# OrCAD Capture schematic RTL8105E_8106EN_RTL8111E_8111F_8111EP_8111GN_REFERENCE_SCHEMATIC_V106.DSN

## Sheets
1 P07. Change Note: title: RTL8105E/8111E/8111F/8111EP/8111GN/8106EN Reference Schematic: Change Notes; rev: A1; company: Realtek Semiconductor Corp.; note: RTL8105E/8111E/8111F/8111EP/8111GN/8106EN Reference Schematic; note: No.2, Innovation Road II, Hsinchu Science Park, Hsinchu 300, Taiwan
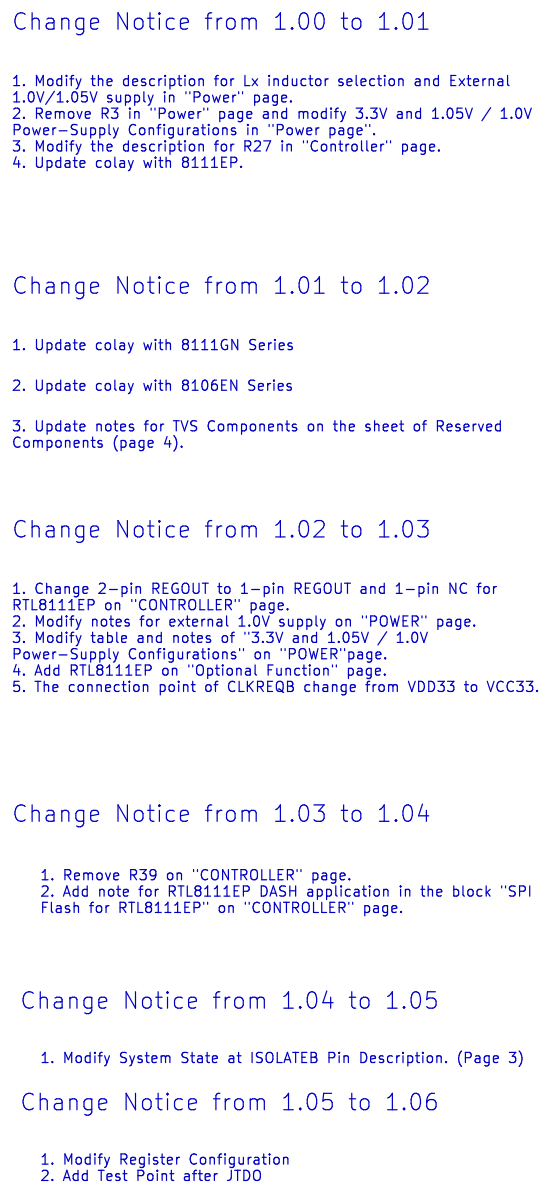
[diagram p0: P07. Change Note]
2 P06. R-BOM: title: RTL8105E/8111E/8111F/8111EP/8111GN/8106EN Reference Schematic: R-BOM
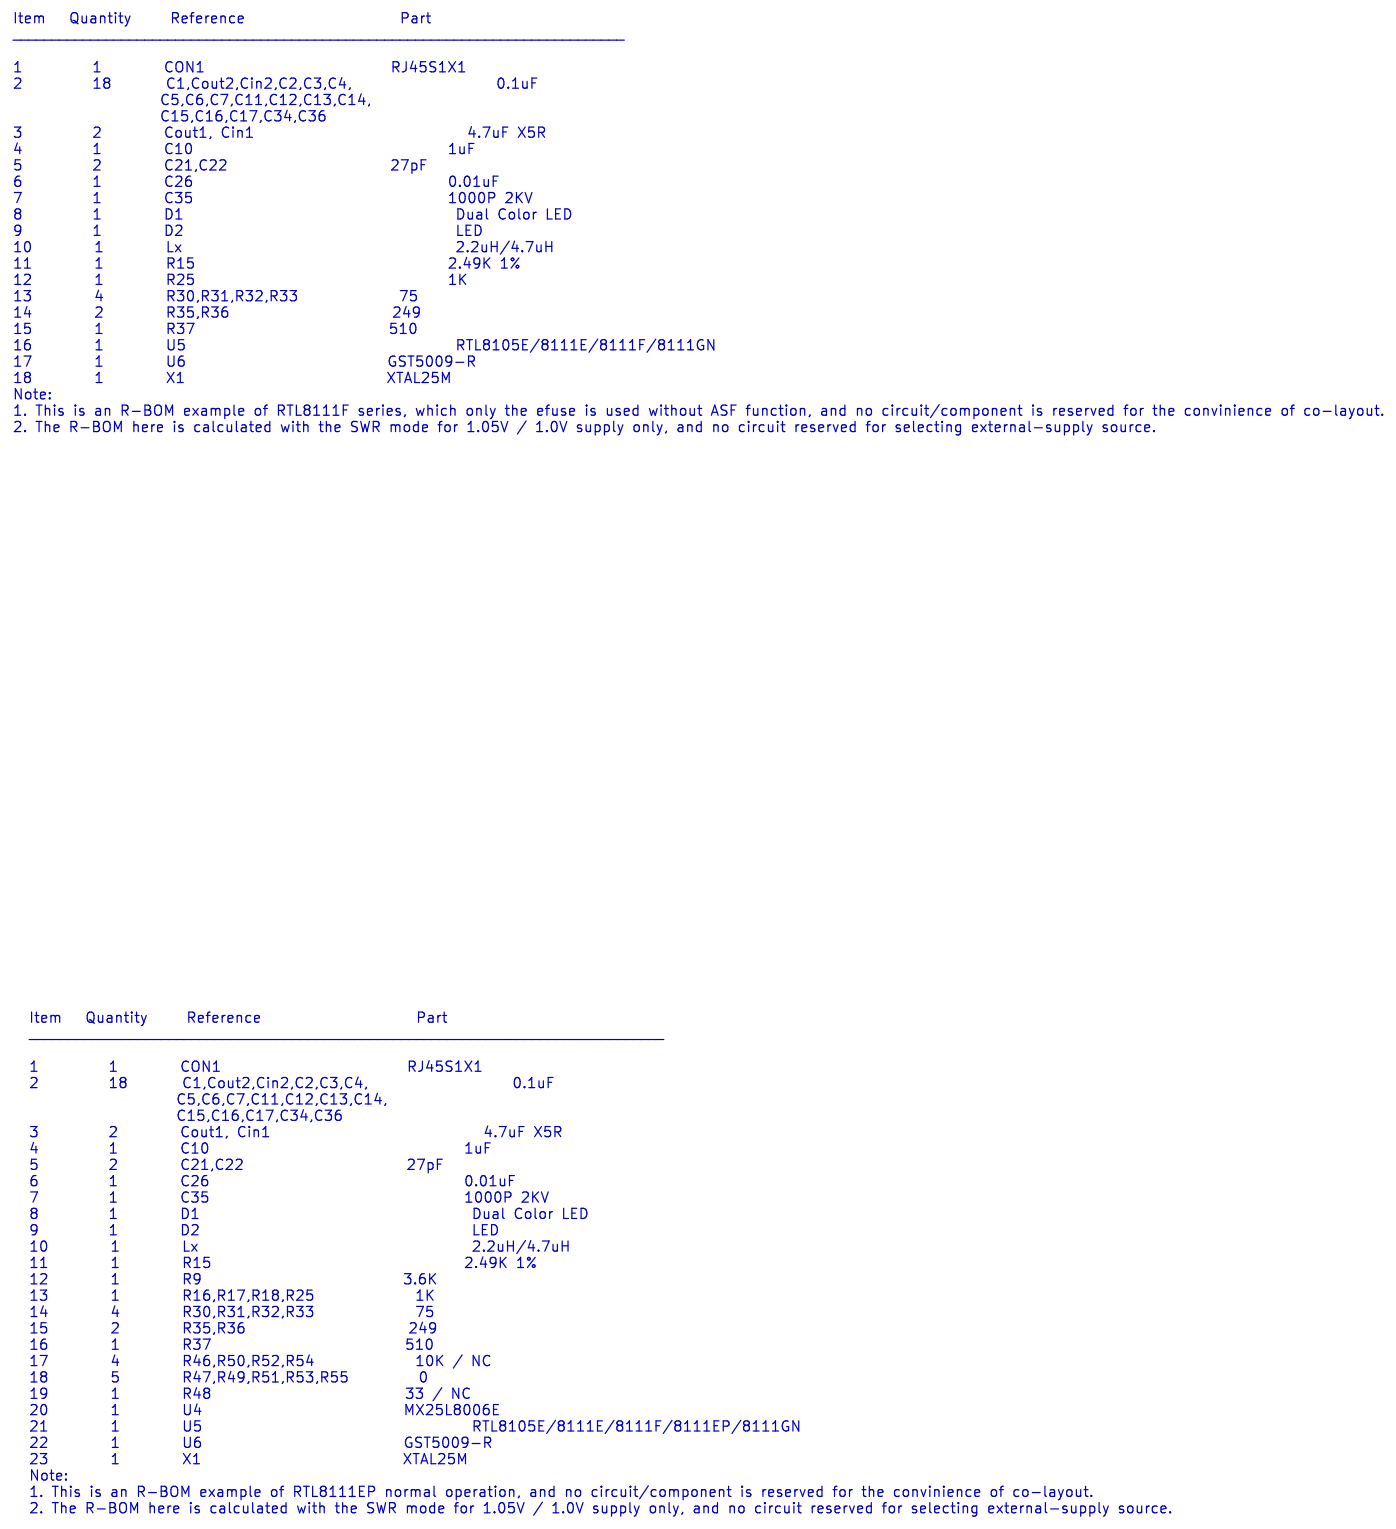
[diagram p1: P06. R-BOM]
3 P04. Reserved Components: size A3; title: RTL8105E/8111E/8111F/8111EP/8111GN/8106EN: Reserved Components
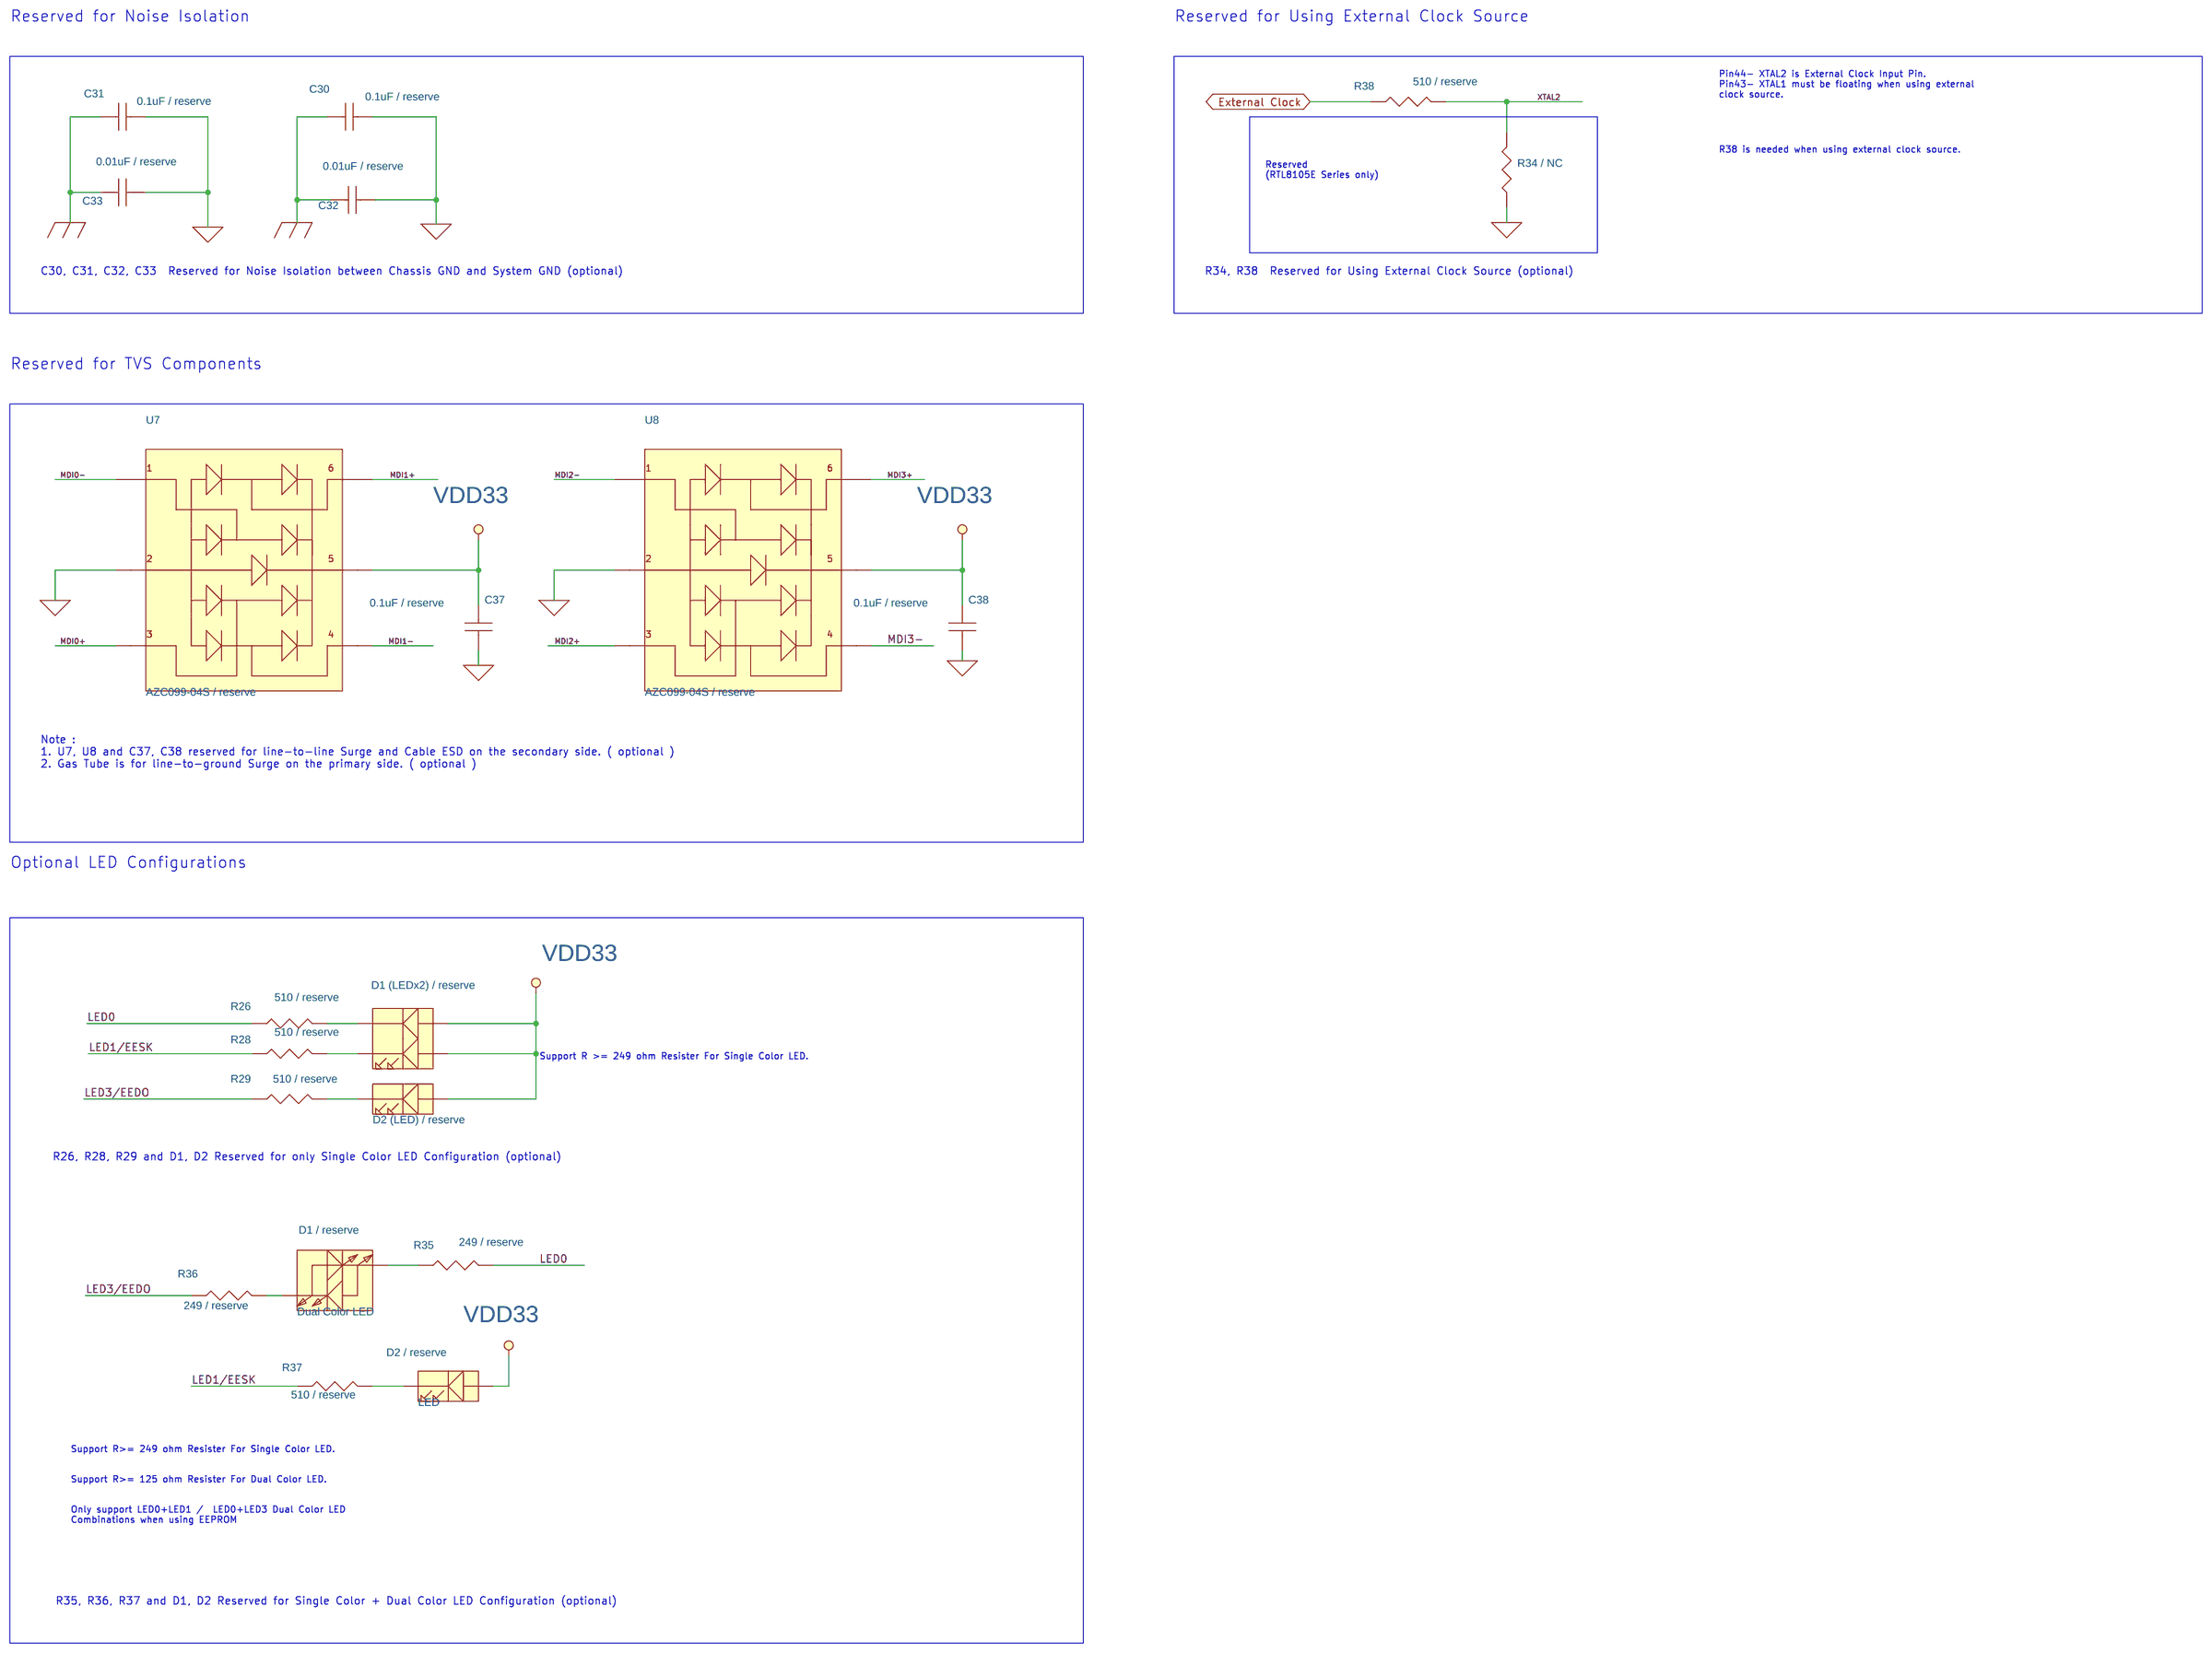
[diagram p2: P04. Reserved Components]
4 P05. Optional Function: size A4; title: RTL8105E/8111E/8111F/8111EP/8111GN/8106EN Reference Schematic: Optional Function
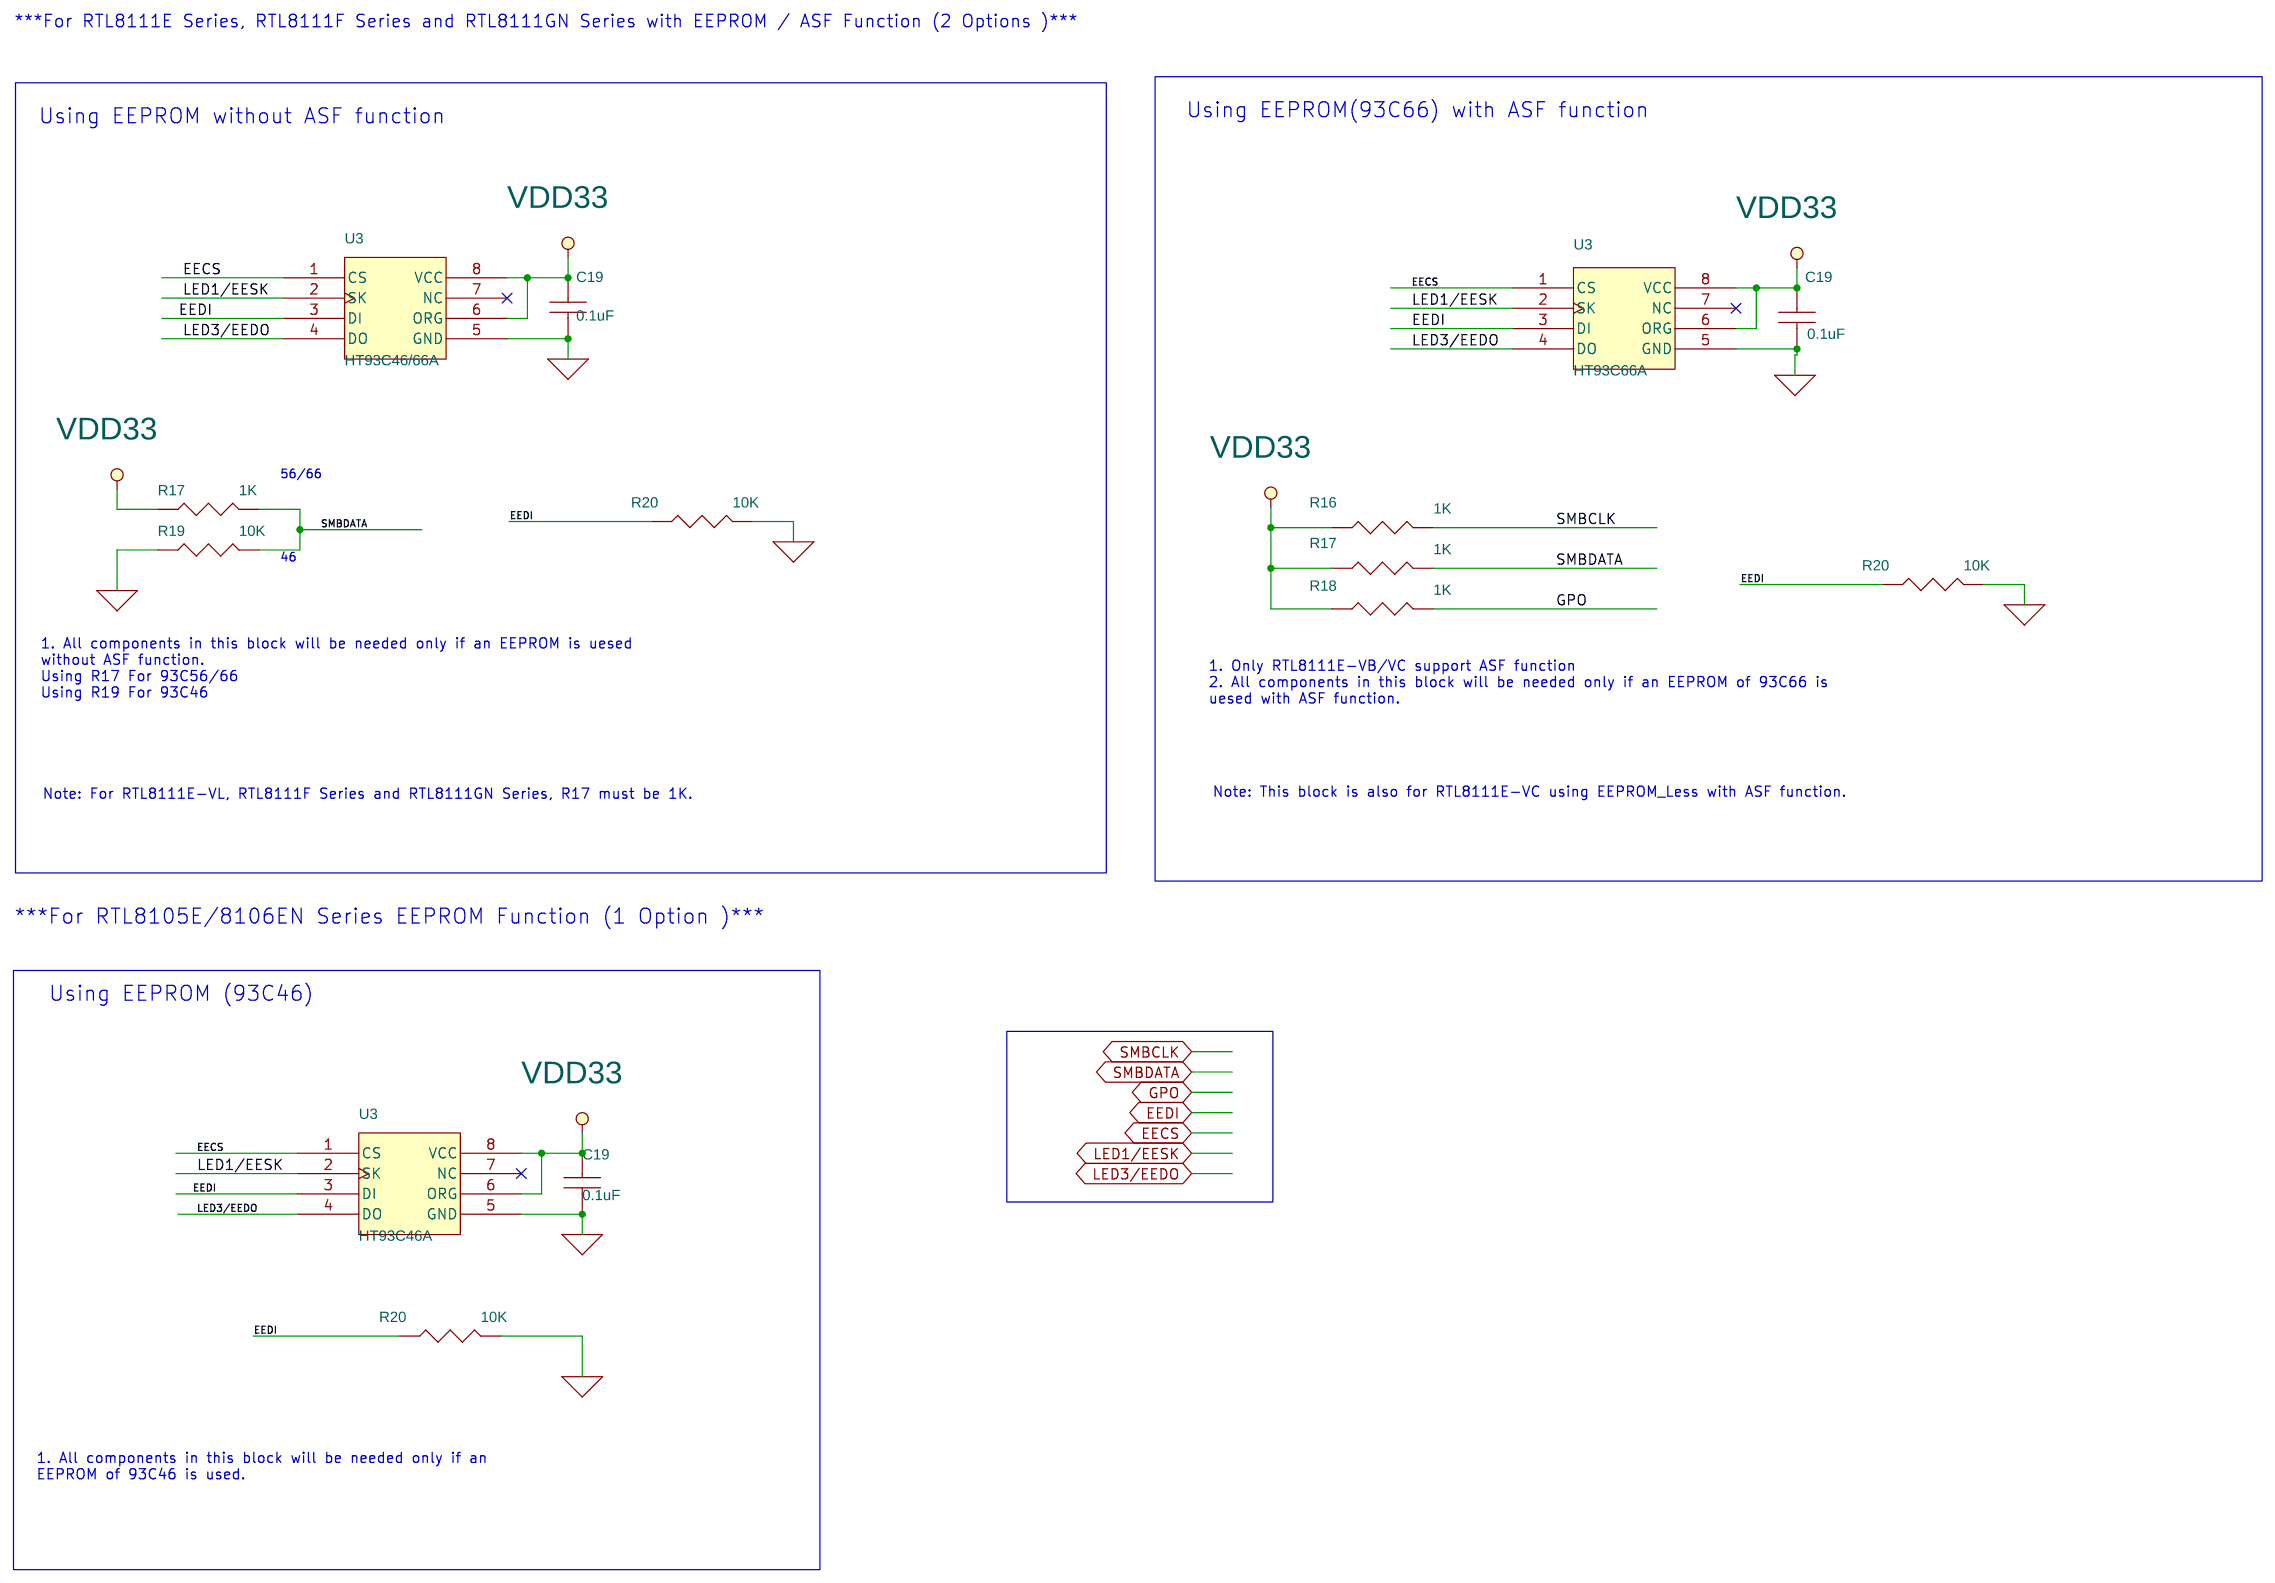
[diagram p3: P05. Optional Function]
5 P01. Index: title: RTL8105E/8111E/8111F/8111EP/8111GN/8106EN Reference Schematic: Index
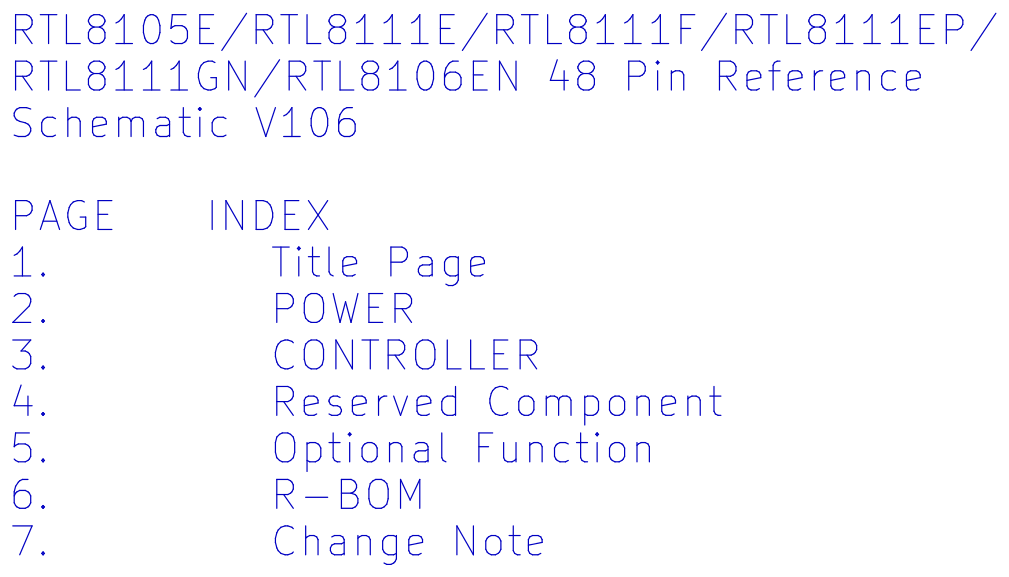
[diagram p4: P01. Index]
6 P02. POWER: size A3; title: RTL8105E/8111E/8111F/8111EP/8111GN/8106EN Reference Schematic: Power
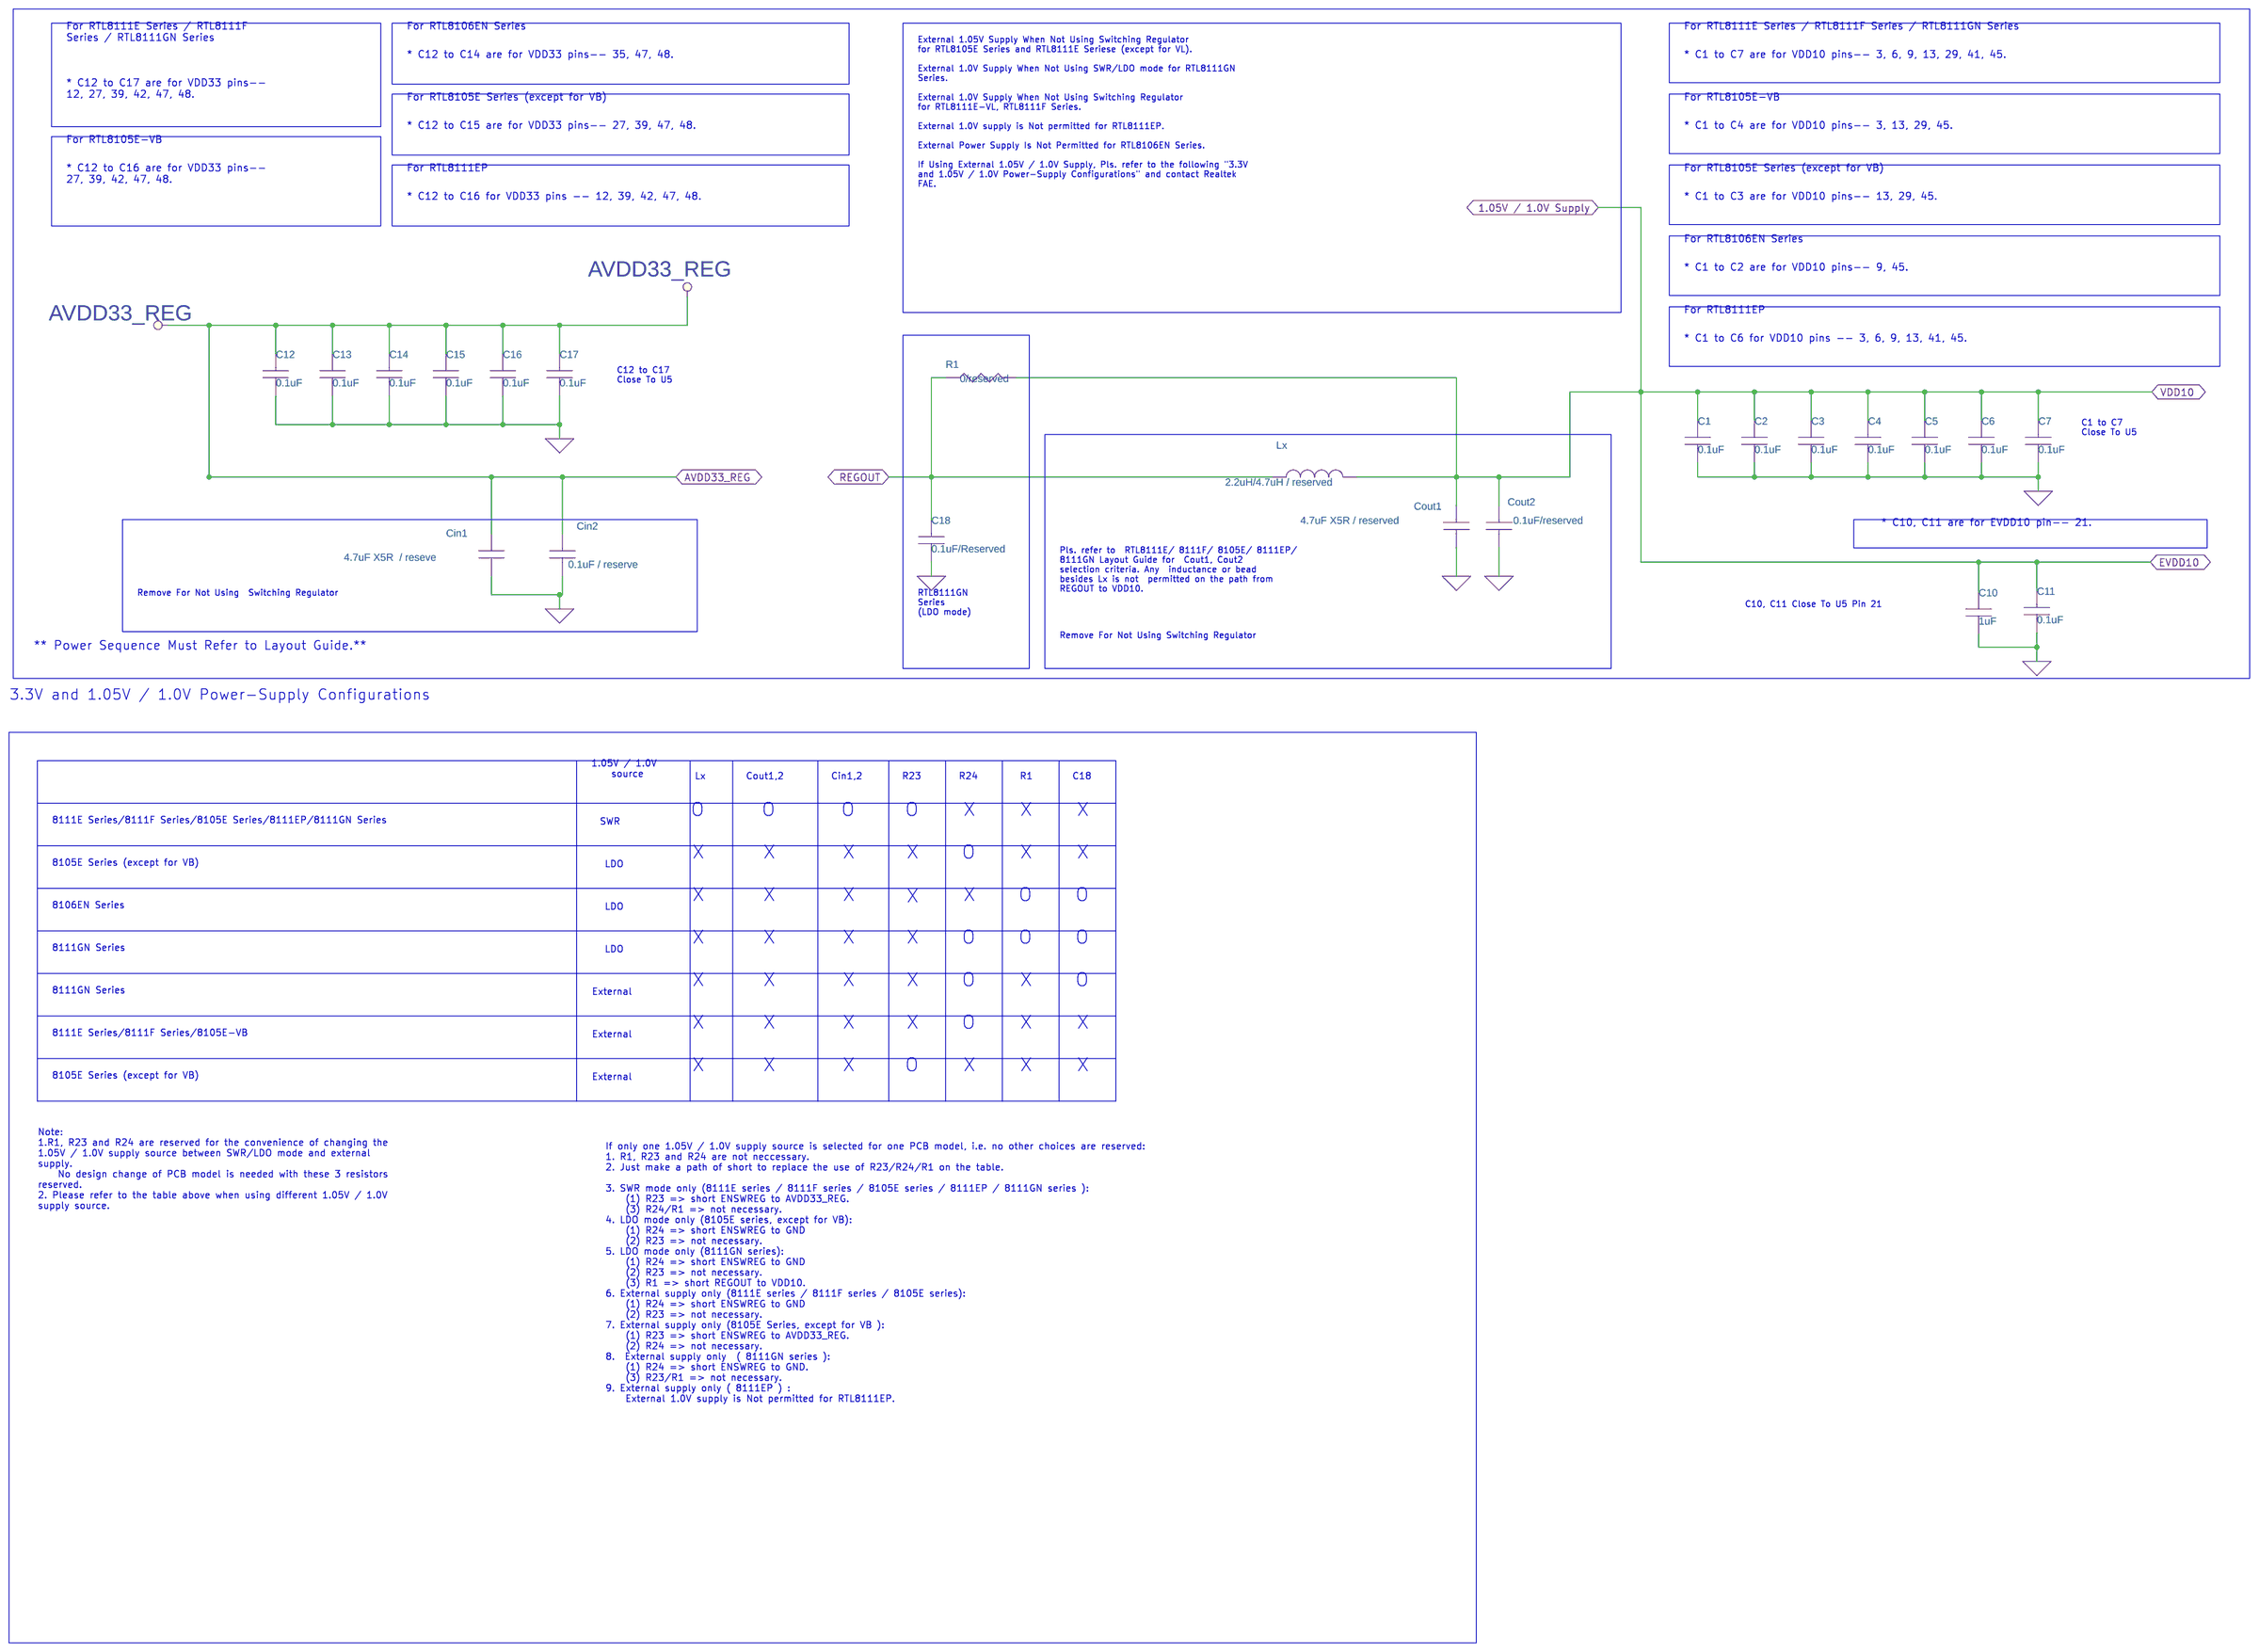
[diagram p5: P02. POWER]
7 P03. CONTROLLER: size A2; title: RTL8105E/8111E/8111F/8111EP/8111GN/8106EN Reference Schematic: Controller
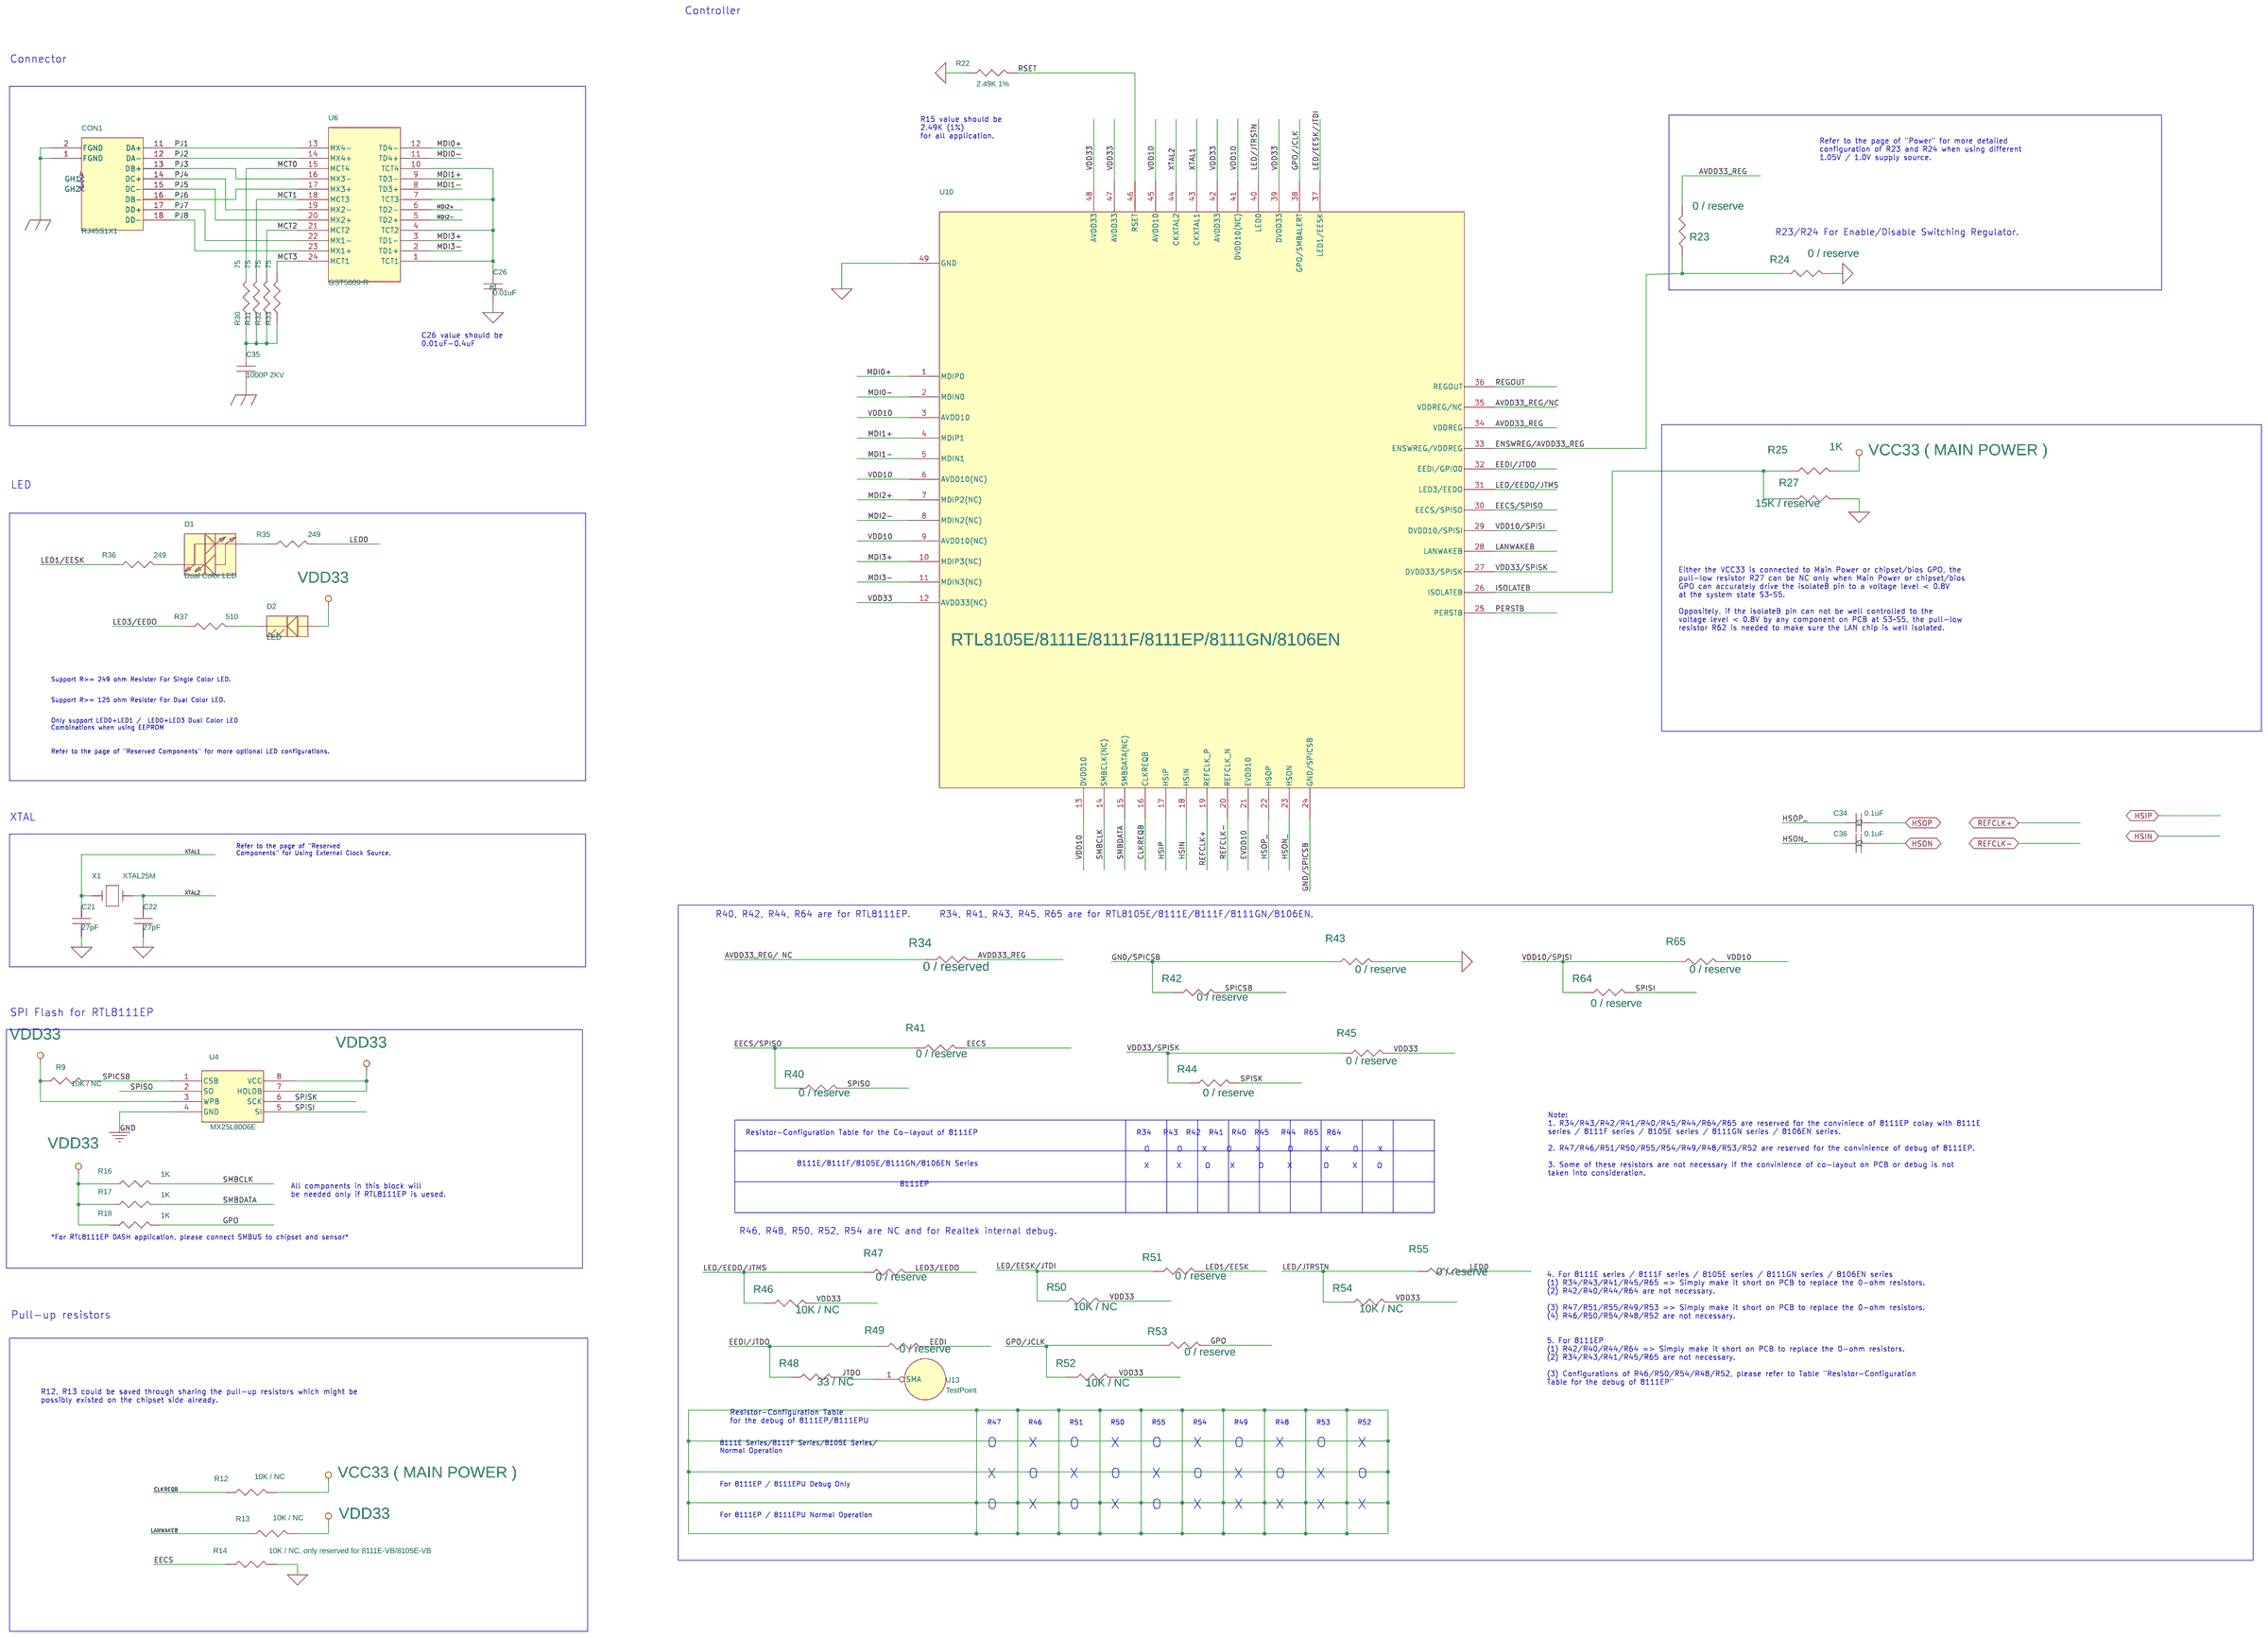
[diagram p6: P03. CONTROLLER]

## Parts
sheet P02. POWER
C1  0.1uF  [C0402C]
C2  0.1uF  [C0402C]
C3  0.1uF  [C0402C]
C4  0.1uF  [C0402C]
C5  0.1uF  [C0402C]
C6  0.1uF  [C0402C]
C7  0.1uF  [C0402C]
C10  1uF  [C0402C]
C11  0.1uF  [C0402C]
C12  0.1uF  [C0402C]
C13  0.1uF  [C0402C]
C14  0.1uF  [C0402C]
C15  0.1uF  [C0402C]
C16  0.1uF  [C0402C]
C17  0.1uF  [C0402C]
C18  0.1uF/Reserved  [C0402C]
Cin1  4.7uF X5R  / reseve  [C1206C]
Cin2  0.1uF / reserve  [C0402C]
Cout1  4.7uF X5R / reserved  [C0805C]
Cout2  0.1uF/reserved  [C0402C]
Lx  2.2uH/4.7uH / reserved  [L\5X5\3.15]
R1  0/reserved  [R0402R]
sheet P03. CONTROLLER
C21  27pF  [C0402C]
C22  27pF  [C0402C]
C26  0.01uF  [C0402C]
C34  0.1uF
C35  1000P 2KV  [C1206C]
C36  0.1uF
CON1  RJ45S1X1  [RJ45S1X1]
D1  Dual Color LED  [LED2X2]
D2  LED  [LED]
R9  10K / NC  [R0402R]
R12  10K / NC  [R0402R]
R13  10K / NC  [R0402R]
R14  10K / NC, only reserved for 8111E-VB/8105E-VB  [R0402R]
R22  2.49K 1%  [R0402R]
R23  0 / reserve  [R0402R]
R24  0 / reserve  [R0402R]
R25  1K  [R0402R]
R27  15K / reserve  [R0402R]
R30  75  [R0402R]
R31  75  [R0402R]
R32  75  [R0402R]
R33  75  [R0402R]
R34  0 / reserved  [R0402R]
R40  0 / reserve  [R0402R]
R41  0 / reserve  [R0402R]
R42  0 / reserve  [R0402R]
R43  0 / reserve  [R0402R]
R44  0 / reserve  [R0402R]
R45  0 / reserve  [R0402R]
R46  10K / NC  [R0402R]
R47  0 / reserve  [R0402R]
R48  33 / NC  [R0402R]
R49  0 / reserve  [R0402R]
R50  10K / NC  [R0402R]
R51  0 / reserve  [R0402R]
R52  10K / NC  [R0402R]
R53  0 / reserve  [R0402R]
R54  10K / NC  [R0402R]
R55  0 / reserve  [R0402R]
R64  0 / reserve  [R0402R]
R65  0 / reserve  [R0402R]
U4  MX25L8006E  [SOIC8]
U6  GST5009-R  [GST5009-LFE9249-R]
U10  RTL8105E/8111E/8111F/8111EP/8111GN/8106EN  [QFN6x6-48]
U13  TestPoint  [SMA]
X1  XTAL25M  [XTAL]
sheet P04. Reserved Components
C30  0.1uF / reserve  [C0402C]
C31  0.1uF / reserve  [C0402C]
C32  0.01uF / reserve  [C0402C]
C33  0.01uF / reserve  [C0402C]
C37  0.1uF / reserve  [C0402C]
C38  0.1uF / reserve  [C0402C]
D1 (LEDx2) / reserve  LEDx2  [LED2X2]
D1 / reserve  Dual Color LED  [LED2X2]
D2 (LED) / reserve  LED  [LED]
D2 / reserve  LED  [LED]
R26  510 / reserve  [R0402R]
R28  510 / reserve  [R0402R]
R29  510 / reserve  [R0402R]
R34 / NC  NC  [R0402R]
R35  249 / reserve  [R0402R]
R35#2  249 / reserve  [R0402R]
R36  249 / reserve  [R0402R]
R36#2  249 / reserve  [R0402R]
R37  510 / reserve  [R0402R]
R37#2  510 / reserve  [R0402R]
R38  510 / reserve  [R0402R]
U7  AZC099-04S / reserve  [SOT23-6L]
U8  AZC099-04S / reserve  [SOT23-6L]
sheet P05. Optional Function
C19  0.1uF  [C0402C]
C19#2  0.1uF  [C0402C]
C19#3  0.1uF  [C0402C]
R16  1K  [R0402R]
R16#2  1K  [R0402R]
R17  1K  [R0402R]
R17#2  1K  [R0402R]
R17#3  1K  [R0402R]
R18  1K  [R0402R]
R18#2  1K  [R0402R]
R19  10K  [R0402R]
R20  10K  [R0402R]
R20#2  10K  [R0402R]
R20#3  10K  [R0402R]
U3  HT93C66A  [SO8-6-1.27]
U3#2  HT93C66A  [SO8-6-1.27]
U3#3  HT93C46A  [SO8-6-1.27]

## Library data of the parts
C1-C3 = CAPACITOR_NON-POL_0: ROOM: c_15
C4-C7 Cout1 Cout2 = CAPACITOR_NON-POL_0: ROOM: vdd18
C10 C11 = CAPACITOR_NON-POL_0: ROOM: vdd15
C12 C15 C16 = CAPACITOR_NON-POL_0: ROOM: 33vaux
C13 C14 C17-C19 C19#2 C19#3 C21 C22 C30-C33 C35 Cin1 Cin2 = CAPACITOR_NON-POL_0
Lx = INDUCTOR_0: ROOM: vdd18
R1 R9 R12-R14 R16 R16#2 R17 R17#2 R17#3 R18 R18#2 R19 R20 R20#2 R20#3 R22-R34 R34 / NC R35 R35#2 R36 R36#2 R37 R37#2 R38 R40-R55 R64 R65 = R
C26 = CAP_NP
C34 = CAP_NP_2
C36-C38 = CAP_NP_1
CON1 = RJ45_2
D1 D1 / reserve = LED_2
D2 D2 (LED) / reserve D2 / reserve = LED_3
U4 = 8-LEAD_SOIC_0
U6 = H5007
U10 = RL5877_84
U13 = SMA
X1 = CRYSTAL_0
D1 (LEDx2) / reserve = LED_1
U7 U8 = 9346_5
U3 U3#2 U3#3 = 9346_4

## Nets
AVDD33_REG: R23.2 R34.2 U10.34(VDDREG)
DGND: C1.2 C2.2 C3.2 C4.2 C5.2 C6.2 C7.2 C10.2 C11.2 C12.2 C13.2 C14.2 C15.2 C16.2 C17.2 C18.2 C19.2 C19#2.2 C19#3.2 C21.2 C22.2 C26.2 C30.2 C31.2 C32.2 C33.2 C37.2 C38.2 Cin1.2 Cin2.2 Cout1.2 Cout2.2 R14.2 R19.1 R20.2 R20#2.2 R20#3.2 R22.1 R24.2 R27.2 R34 / NC.1 R43.2 U3.5(GND) U3#2.5(GND) U3#3.5(GND) U7.2 U8.2 U10.49(GND)
ENSWREG/AVDD33_REG: R23.1 R24.1 U10.33(ENSWREG/VDDREG)
GND POWER: U4.4(GND)
VCC33 ( Main Power ): R12.2 R25.2
VDD10: R65.2 U10.3(AVDD10) U10.6(AVDD10(NC)) U10.9(AVDD10(NC)) U10.13(DVDD10) U10.41(DVDD10(NC)) U10.45(AVDD10)
VDD33: C12.1 C13.1 C14.1 C15.1 C16.1 C17.1 C19.1 C19#2.1 C19#3.1 C37.1 C38.1 Cin1.1 Cin2.1 D1 (LEDx2) / reserve.1 D1 (LEDx2) / reserve.2 D2.1 D2 (LED) / reserve.1 D2 / reserve.1 R9.1 R13.2 R16.1 R16#2.1 R17.1 R17#2.1 R17#3.1 R18.1 R18#2.1 R45.2 R46.2 R50.2 R52.2 R54.2 U3.6(ORG) U3.8(VCC) U3#2.6(ORG) U3#2.8(VCC) U3#3.6(ORG) U3#3.8(VCC) U4.3(WPB) U4.7(HOLDB) U4.8(VCC) U7.5 U8.5 U10.12(AVDD33(NC)) U10.39(DVDD33) U10.42(AVDD33) U10.47(AVDD33) U10.48(AVDD33)
1.05V / 1.0V Supply: C1.1 C2.1 C3.1 C4.1 C5.1 C6.1 C7.1 C10.1 C11.1 Cout1.1 Cout2.1 Lx.2 R1.2
  REFCLK+: U10.19(REFCLK_P)
 EEDI: U3.3(DI) U3#3.3(DI)
AVDD33_REG/ NC: R34.1
AVDD33_REG/NC: U10.35(VDDREG/NC)
CLKREQB: R12.1 U10.16(CLKREQB)
EECS: R14.1 R41.2
EECS (page P05. Optional Function): U3.1(CS) U3#2.1(CS) U3#3.1(CS)
EECS/SPISO: R40.1 R41.1 U10.30(EECS/SPISO)
EEDI: R49.2
EEDI (page P05. Optional Function): R20.1 R20#2.1 R20#3.1 U3#2.3(DI)
EEDI/JTDO: R48.1 R49.1 U10.32(EEDI/GPIO0)
EVDD10: U10.21(EVDD10)
External Clock: R38.1
FGND: C30.1 C31.1 C32.1 C33.1 C35.2 CON1.1(FGND) CON1.2(FGND)
GND/SPICSB: R42.1 R43.1 U10.24(GND/SPICSB)
GPO: R18.2 R53.2
GPO (page P05. Optional Function): R18#2.2
GPO/JCLK: R52.1 R53.1 U10.38(GPO/SMBALERT)
HSIN: U10.18(HSIN)
HSIP: U10.17(HSIP)
HSON: C36.2
HSON_: C36.1 U10.23(HSON)
HSOP: C34.2
HSOP_: C34.1 U10.22(HSOP)
ISOLATEB: R25.1 R27.1 U10.26(ISOLATEB)
JTDO: R48.2 U13.1(SMA)
LANWAKEB: R13.1 U10.28(LANWAKEB)
LED0: R35.2 R55.2
LED0 (page P04. Reserved Components): R26.1 R35#2.2
LED1/EESK: R36.1 R51.2
LED1/EESK (page P04. Reserved Components): R28.1 R37#2.1
LED1/EESK (page P05. Optional Function): U3.2(SK) U3#2.2(SK) U3#3.2(SK)
LED3/EEDO: R37.1 R47.2
LED3/EEDO (page P04. Reserved Components): R29.1 R36#2.1
LED3/EEDO (page P05. Optional Function): U3.4(DO) U3#2.4(DO) U3#3.4(DO)
LED/EEDO/JTMS: R46.1 R47.1 U10.31(LED3/EEDO)
LED/EESK/JTDI: R50.1 R51.1 U10.37(LED1/EESK)
LED/JTRSTN: R54.1 R55.1 U10.40(LED0)
MCT0: R30.2 U6.15(MCT4)
MCT1: R31.2 U6.18(MCT3)
MCT2: R32.2 U6.21(MCT2)
MCT3: R33.2 U6.24(MCT1)
MDI0+: U6.12(TD4-) U10.1(MDIP0)
MDI0+ (page P04. Reserved Components): U7.3
MDI0-: U6.11(TD4+) U10.2(MDIN0)
MDI0- (page P04. Reserved Components): U7.1
MDI1+: U6.9(TD3-) U10.4(MDIP1)
MDI1+ (page P04. Reserved Components): U7.6
MDI1-: U6.8(TD3+) U10.5(MDIN1)
MDI1- (page P04. Reserved Components): U7.4
MDI2+: U6.6(TD2-) U10.7(MDIP2(NC))
MDI2+ (page P04. Reserved Components): U8.3
MDI2-: U6.5(TD2+) U10.8(MDIN2(NC))
MDI2- (page P04. Reserved Components): U8.1
MDI3+: U6.3(TD1-) U10.10(MDIP3(NC))
MDI3+ (page P04. Reserved Components): U8.6
MDI3-: U6.2(TD1+) U10.11(MDIN3(NC))
MDI3- (page P04. Reserved Components): U8.4
PERSTB: U10.25(PERSTB)
PJ1: CON1.11(DA+) U6.13(MX4-)
PJ2: CON1.12(DA-) U6.14(MX4+)
PJ3: CON1.13(DB+) U6.16(MX3-)
PJ4: CON1.14(DC+) U6.19(MX2-)
PJ5: CON1.15(DC-) U6.20(MX2+)
PJ6: CON1.16(DB-) U6.17(MX3+)
PJ7: CON1.17(DD+) U6.22(MX1-)
PJ8: CON1.18(DD-) U6.23(MX1+)
REFCLK-: U10.20(REFCLK_N)
REGOUT: C18.1 Lx.1 R1.1
REGOUT (page P03. CONTROLLER): U10.36(REGOUT)
RSET: R22.2 U10.46(RSET)
SMBCLK: R16.2 U10.14(SMBCLK(NC))
SMBCLK (page P05. Optional Function): R16#2.2
SMBDATA: R17.2 U10.15(SMBDATA(NC))
SMBDATA (page P05. Optional Function): R17#2.2 R17#3.2 R19.2
SPICSB: R9.2 R42.2 U4.1(CSB)
SPISI: R64.2 U4.5(SI)
SPISK: R44.2 U4.6(SCK)
SPISO: R40.2 U4.2(SO)
VDD10/SPISI: R64.1 R65.1 U10.29(DVDD10/SPISI)
VDD33/SPISK: R44.1 R45.1 U10.27(DVDD33/SPISK)
XTAL1: C21.1 U10.43(CKXTAL1) X1.1
XTAL2: C22.1 U10.44(CKXTAL2) X1.2
XTAL2 (page P04. Reserved Components): R34 / NC.2 R38.2
N48283: C35.1 R30.1 R31.1 R32.1 R33.1
N17380918: C26.1 U6.1(TCT1) U6.4(TCT2) U6.7(TCT3) U6.10(TCT4)
N19422524: D1.2 R36.2
N19422845: D1.1 R35.1
N19450336: D2.2 R37.2
N20002596: D1 (LEDx2) / reserve.3 R26.2
N20002600: D1 (LEDx2) / reserve.4 R28.2
N20002614: D2 (LED) / reserve.2 R29.2
N20007964: D2 / reserve.2 R37#2.2
N20008009: D1 / reserve.1 R35#2.1
N20008023: D1 / reserve.2 R36#2.2

Not connected (* = marked no-connect by the designer): CON1 3(GH2)* 4(GH1)*; U3 7(NC)*; U3#2 7(NC)*; U3#3 7(NC)*

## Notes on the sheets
sheet 1
- Change Notice from 1.00 to 1.01
- 1. Modify the description for Lx inductor selection and External
  1.0V/1.05V supply in "Power" page.
  2. Remove R3 in "Power" page and modify 3.3V and 1.05V / 1.0V
  Power-Supply Configurations in "Power page".
  3. Modify the description for R27 in "Controller" page.
  4. Update colay with 8111EP.
- Change Notice from 1.01 to 1.02
- 1. Update colay with 8111GN Series
- 2. Update colay with 8106EN Series
- 3. Update notes for TVS Components on the sheet of Reserved
  Components (page 4).
- Change Notice from 1.02 to 1.03
- 1. Change 2-pin REGOUT to 1-pin REGOUT and 1-pin NC for
  RTL8111EP on "CONTROLLER" page.
  2. Modify notes for external 1.0V supply on "POWER" page.
  3. Modify table and notes of "3.3V and 1.05V / 1.0V
  Power-Supply Configurations" on "POWER"page.
  4. Add RTL8111EP on "Optional Function" page.
  5. The connection point of CLKREQB change from VDD33 to VCC33.
- Change Notice from 1.03 to 1.04
- 1. Remove R39 on "CONTROLLER" page.
  2. Add note for RTL8111EP DASH application in the block "SPI
  Flash for RTL8111EP" on "CONTROLLER" page.
- Change Notice from 1.04 to 1.05
- 1. Modify System State at ISOLATEB Pin Description. (Page 3)
- Change Notice from 1.05 to 1.06
- 1. Modify Register Configuration
  2. Add Test Point after JTDO
sheet 2
- Item   Quantity     Reference                    Part
  _______________________________________________________________________________
  1         1        CON1                        RJ45S1X1
  2         18       C1,Cout2,Cin2,C2,C3,C4,	     0.1uF
                     C5,C6,C7,C11,C12,C13,C14,
                     C15,C16,C17,C34,C36
  3         2        Cout1, Cin1	                 4.7uF X5R
  4         1        C10	                         1uF
  5         2        C21,C22                     27pF
  6         1        C26	                         0.01uF
  7         1        C35	                         1000P 2KV
  8         1        D1	                          Dual Color LED
  9         1        D2	                          LED
  10        1        Lx	                          2.2uH/4.7uH
  11        1        R15	                         2.49K 1%
  12        1        R25	                         1K
  13        4        R30,R31,R32,R33             75
  14        2        R35,R36                     249
  15        1        R37                         510
  16        1        U5	                          RTL8105E/8111E/8111F/8111GN
  17        1        U6                          GST5009-R
  18        1        X1                          XTAL25M
  Note:
  1. This is an R-BOM example of RTL8111F series, which only the efuse is used without ASF function, and no circuit/component is reserved for the convinience of co-layout.
  2. The R-BOM here is calculated with the SWR mode for 1.05V / 1.0V supply only, and no circuit reserved for selecting external-supply source.
- Item   Quantity     Reference                    Part
  __________________________________________________________________________________
  1         1        CON1                        RJ45S1X1
  2         18       C1,Cout2,Cin2,C2,C3,C4,	     0.1uF
                     C5,C6,C7,C11,C12,C13,C14,
                     C15,C16,C17,C34,C36
  3         2        Cout1, Cin1	                 4.7uF X5R
  4         1        C10	                         1uF
  5         2        C21,C22                     27pF
  6         1        C26	                         0.01uF
  7         1        C35	                         1000P 2KV
  8         1        D1	                          Dual Color LED
  9         1        D2	                          LED
  10        1        Lx	                          2.2uH/4.7uH
  11        1        R15	                         2.49K 1%
  12        1        R9                          3.6K
  13        1        R16,R17,R18,R25             1K
  14        4        R30,R31,R32,R33             75
  15        2        R35,R36                     249
  16        1        R37                         510
  17        4        R46,R50,R52,R54             10K / NC
  18        5        R47,R49,R51,R53,R55         0
  19        1        R48                         33 / NC
  20        1        U4                          MX25L8006E
  21        1        U5	                          RTL8105E/8111E/8111F/8111EP/8111GN
  22        1        U6                          GST5009-R
  23        1        X1                          XTAL25M
  Note:
  1. This is an R-BOM example of RTL8111EP normal operation, and no circuit/component is reserved for the convinience of co-layout.
  2. The R-BOM here is calculated with the SWR mode for 1.05V / 1.0V supply only, and no circuit reserved for selecting external-supply source.
sheet 3
- Reserved for Noise Isolation
- Reserved for Using External Clock Source
- Pin44- XTAL2 is External Clock Input Pin.
  Pin43- XTAL1 must be floating when using external
  clock source.
- R38 is needed when using external clock source.
- Reserved
  (RTL8105E Series only)
- C30, C31, C32, C33  Reserved for Noise Isolation between Chassis GND and System GND (optional)
- R34, R38  Reserved for Using External Clock Source (optional)
- Reserved for TVS Components
- Note :
  1. U7, U8 and C37, C38 reserved for line-to-line Surge and Cable ESD on the secondary side. ( optional )
  2. Gas Tube is for line-to-ground Surge on the primary side. ( optional )
- Optional LED Configurations
- Support R >= 249 ohm Resister For Single Color LED.
- R26, R28, R29 and D1, D2 Reserved for only Single Color LED Configuration (optional)
- Support R>= 249 ohm Resister For Single Color LED.
- Support R>= 125 ohm Resister For Dual Color LED.
- Only support LED0+LED1 /  LED0+LED3 Dual Color LED
  Combinations when using EEPROM
- R35, R36, R37 and D1, D2 Reserved for Single Color + Dual Color LED Configuration (optional)
sheet 4
- ***For RTL8111E Series, RTL8111F Series and RTL8111GN Series with EEPROM / ASF Function (2 Options )***
- Using EEPROM(93C66) with ASF function
- Using EEPROM without ASF function
- 56/66
- 46
- 1. All components in this block will be needed only if an EEPROM is uesed
  without ASF function.
  Using R17 For 93C56/66
  Using R19 For 93C46
- 1. Only RTL8111E-VB/VC support ASF function
  2. All components in this block will be needed only if an EEPROM of 93C66 is
  uesed with ASF function.
- Note: For RTL8111E-VL, RTL8111F Series and RTL8111GN Series, R17 must be 1K.
- Note: This block is also for RTL8111E-VC using EEPROM_Less with ASF function.
- ***For RTL8105E/8106EN Series EEPROM Function (1 Option )***
- Using EEPROM (93C46)
- 1. All components in this block will be needed only if an
  EEPROM of 93C46 is used.
sheet 5
- RTL8105E/RTL8111E/RTL8111F/RTL8111EP/
  RTL8111GN/RTL8106EN 48 Pin Reference
  Schematic V106
  PAGE    INDEX
  1.          Title Page
  2.          POWER
  3.          CONTROLLER
  4.          Reserved Component
  5.          Optional Function
  6.          R-BOM
  7.          Change Note
sheet 6
- For RTL8111E Series / RTL8111F
  Series / RTL8111GN Series
- For RTL8106EN Series
- For RTL8111E Series / RTL8111F Series / RTL8111GN Series
- External 1.05V Supply When Not Using Switching Regulator
  for RTL8105E Series and RTL8111E Seriese (except for VL).
  External 1.0V Supply When Not Using SWR/LDO mode for RTL8111GN
  Series.
  External 1.0V Supply When Not Using Switching Regulator
  for RTL8111E-VL, RTL8111F Series.
  External 1.0V supply is Not permitted for RTL8111EP.
  External Power Supply Is Not Permitted for RTL8106EN Series.
  If Using External 1.05V / 1.0V Supply, Pls. refer to the following "3.3V
  and 1.05V / 1.0V Power-Supply Configurations" and contact Realtek
  FAE.
- * C12 to C14 are for VDD33 pins-- 35, 47, 48.
- * C1 to C7 are for VDD10 pins-- 3, 6, 9, 13, 29, 41, 45.
- * C12 to C17 are for VDD33 pins--
  12, 27, 39, 42, 47, 48.
- For RTL8105E Series (except for VB)
- For RTL8105E-VB
- * C12 to C15 are for VDD33 pins-- 27, 39, 47, 48.
- * C1 to C4 are for VDD10 pins-- 3, 13, 29, 45.
- For RTL8105E-VB
- * C12 to C16 are for VDD33 pins--
  27, 39, 42, 47, 48.
- For RTL8111EP
- For RTL8105E Series (except for VB)
- * C12 to C16 for VDD33 pins -- 12, 39, 42, 47, 48.
- * C1 to C3 are for VDD10 pins-- 13, 29, 45.
- For RTL8106EN Series
- * C1 to C2 are for VDD10 pins-- 9, 45.
- For RTL8111EP
- * C1 to C6 for VDD10 pins -- 3, 6, 9, 13, 41, 45.
- C12 to C17
  Close To U5
- C1 to C7
  Close To U5
- * C10, C11 are for EVDD10 pin-- 21.
- Pls. refer to  RTL8111E/ 8111F/ 8105E/ 8111EP/
  8111GN Layout Guide for  Cout1, Cout2
  selection criteria. Any  inductance or bead
  besides Lx is not  permitted on the path from
  REGOUT to VDD10.
- Remove For Not Using  Switching Regulator
- RTL8111GN
  Series
  (LDO mode)
- C10, C11 Close To U5 Pin 21
- Remove For Not Using Switching Regulator
- ** Power Sequence Must Refer to Layout Guide.**
- 3.3V and 1.05V / 1.0V Power-Supply Configurations
- 1.05V / 1.0V
      source
- Lx
- Cout1,2
- Cin1,2
- R23
- R24
- R1
- C18
- O
- O
- O
- O
- X
- X
- X
- 8111E Series/8111F Series/8105E Series/8111EP/8111GN Series
- SWR
- X
- X
- X
- X
- O
- X
- X
- 8105E Series (except for VB)
- LDO
- 8106EN Series
- X
- X
- X
- X
- X
- O
- O
- LDO
- X
- X
- X
- X
- O
- O
- O
- 8111GN Series
- LDO
- X
- X
- X
- X
- O
- X
- O
- 8111GN Series
- External
- X
- X
- X
- X
- O
- X
- X
- 8111E Series/8111F Series/8105E-VB
- External
- X
- X
- X
- O
- X
- X
- X
- 8105E Series (except for VB)
- External
- Note:
  1.R1, R23 and R24 are reserved for the convenience of changing the
  1.05V / 1.0V supply source between SWR/LDO mode and external
  supply.
      No design change of PCB model is needed with these 3 resistors
  reserved.
  2. Please refer to the table above when using different 1.05V / 1.0V
  supply source.
- If only one 1.05V / 1.0V supply source is selected for one PCB model, i.e. no other choices are reserved:
  1. R1, R23 and R24 are not neccessary.
  2. Just make a path of short to replace the use of R23/R24/R1 on the table.
  3. SWR mode only (8111E series / 8111F series / 8105E series / 8111EP / 8111GN series ):
      (1) R23 => short ENSWREG to AVDD33_REG.
      (3) R24/R1 => not necessary.
  4. LDO mode only (8105E series, except for VB):
      (1) R24 => short ENSWREG to GND
      (2) R23 => not necessary.
  5. LDO mode only (8111GN series):
      (1) R24 => short ENSWREG to GND
      (2) R23 => not necessary.
      (3) R1 => short REGOUT to VDD10.
  6. External supply only (8111E series / 8111F series / 8105E series):
      (1) R24 => short ENSWREG to GND
      (2) R23 => not necessary.
  7. External supply only (8105E Series, except for VB ):
      (1) R23 => short ENSWREG to AVDD33_REG.
      (2) R24 => not necessary.
  8.  External supply only  ( 8111GN series ):
      (1) R24 => short ENSWREG to GND.
      (3) R23/R1 => not necessary.
  9. External supply only ( 8111EP ) :
      External 1.0V supply is Not permitted for RTL8111EP.
sheet 7
- Controller
- Connector
- R15 value should be
  2.49K (1%)
  for all application.
- Refer to the page of "Power" for more detailed
  configuration of R23 and R24 when using different
  1.05V / 1.0V supply source.
- R23/R24 For Enable/Disable Switching Regulator.
- C26 value should be
  0.01uF-0.4uF
- LED
- Either the VCC33 is connected to Main Power or chipset/bios GPO, the
  pull-low resistor R27 can be NC only when Main Power or chipset/bios
  GPO can accurately drive the isolateB pin to a voltage level < 0.8V
  at the system state S3~S5.
  Oppositely, if the isolateB pin can not be well controlled to the
  voltage level < 0.8V by any component on PCB at S3~S5, the pull-low
  resistor R62 is needed to make sure the LAN chip is well isolated.
- Support R>= 249 ohm Resister For Single Color LED.
- Support R>= 125 ohm Resister For Dual Color LED.
- Only support LED0+LED1 /  LED0+LED3 Dual Color LED
  Combinations when using EEPROM
- Refer to the page of "Reserved Components" for more optional LED configurations.
- XTAL
- Refer to the page of "Reserved
  Components" for Using External Clock Source.
- R40, R42, R44, R64 are for RTL8111EP.      R34, R41, R43, R45, R65 are for RTL8105E/8111E/8111F/8111GN/8106EN.
- SPI Flash for RTL8111EP
- Note:
  1. R34/R43/R42/R41/R40/R45/R44/R64/R65 are reserved for the conviniece of 8111EP colay with 8111E
  series / 8111F series / 8105E series / 8111GN series / 8106EN series.
  2. R47/R46/R51/R50/R55/R54/R49/R48/R53/R52 are reserved for the convinience of debug of 8111EP.
  3. Some of these resistors are not necessary if the convinience of co-layout on PCB or debug is not
  taken into consideration.
- Resistor-Configuration Table for the Co-layout of 8111EP
- R34   R43  R42  R41  R40  R45   R44  R65  R64
    O       O     X     O      X       O        X      O     X
    X       X      O     X      O      X        O      X     O
- 8111E/8111F/8105E/8111GN/8106EN Series
- All components in this block will
  be needed only if RTL8111EP is uesed.
- 8111EP
- R46, R48, R50, R52, R54 are NC and for Realtek internal debug.
- *For RTL8111EP DASH application, please connect SMBUS to chipset and sensor*
- 4. For 8111E series / 8111F series / 8105E series / 8111GN series / 8106EN series
  (1) R34/R43/R41/R45/R65 => Simply make it short on PCB to replace the 0-ohm resistors.
  (2) R42/R40/R44/R64 are not necessary.
  (3) R47/R51/R55/R49/R53 => Simply make it short on PCB to replace the 0-ohm resistors.
  (4) R46/R50/R54/R48/R52 are not necessary.
  5. For 8111EP
  (1) R42/R40/R44/R64 => Simply make it short on PCB to replace the 0-ohm resistors.
  (2) R34/R43/R41/R45/R65 are not necessary.
  (3) Configurations of R46/R50/R54/R48/R52, please refer to Table "Resistor-Configuration
  Table for the debug of 8111EP"
- Pull-up resistors
- R12, R13 could be saved through sharing the pull-up resistors which might be
  possibly existed on the chipset side already.
- Resistor-Configuration Table
  for the debug of 8111EP/8111EPU
- R47
- R46
- R51
- R50
- R55
- R54
- R49
- R48
- R53
- R52
- O
- X
- O
- X
- O
- X
- O
- X
- O
- X
- 8111E Series/8111F Series/8105E Series/
  Normal Operation
- X
- O
- X
- O
- X
- O
- X
- O
- X
- O
- For 8111EP / 8111EPU Debug Only
- O
- X
- O
- X
- O
- X
- X
- X
- X
- X
- For 8111EP / 8111EPU Normal Operation
